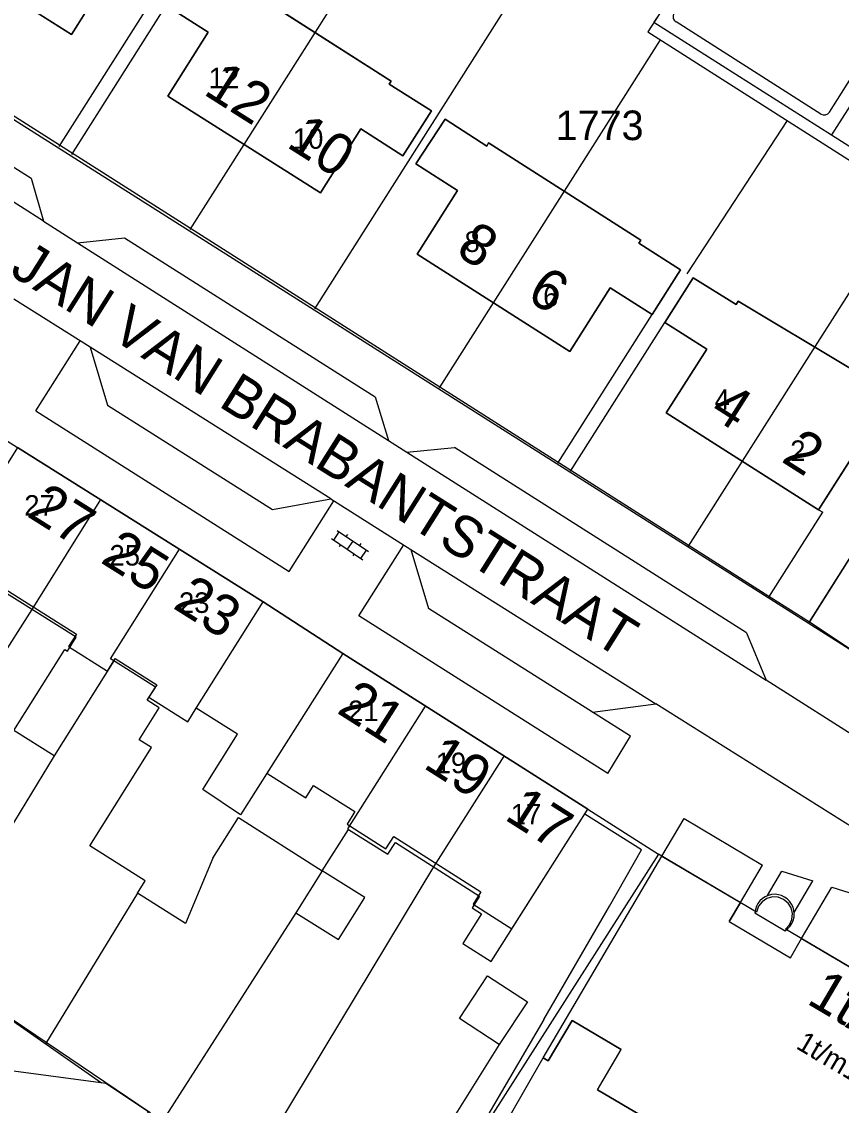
# Model space of a CAD drawing. Extents: x 148816 to 151297, y 399515 to 402500.
# Drawn here: x 149845.7 to 149895.6, y 400300.6 to 400366.5 of the extents above; entities that cross this region are included whole.
import ezdxf

# ---------------------------------------------------------------- set-up
doc = ezdxf.new("R2010")
doc.units = 0
for name, color, linetype in [('B01 Hoofdgebouw  [D] Norm', 7, 'Continuous'), ('B01 Hoofdgebouw  [T] Norm', 7, 'Continuous'), ('B01 hoofgebouw', 7, 'Continuous'), ('B02 Bijgebouw  [D] Norm', 7, 'Continuous'), ('B03 Overig opstal  [D] Norm', 7, 'Continuous'), ('B07 Tussenmuur  [D] Norm', 7, 'Continuous'), ('G01 perceelsgrens', 7, 'Continuous'), ('S02 Open verharding  Norm', 7, 'Continuous'), ('T04 Haag heg  [D] Gem', 7, 'Continuous'), ('V00 Kant verharding algemeen  [T] Norm', 7, 'Continuous'), ('V00 Kant verharding algemeen secundair  [T] Gem', 7, 'Continuous'), ('Z01 perceelnummer', 7, 'Continuous'), ('Z02 huisnummer', 7, 'Continuous'), ('Z02 Huisnummer  [Tekst] Norm', 7, 'Continuous'), ('Z06 straatnaam', 7, 'Continuous')]:
    doc.layers.add(name, color=color, linetype=linetype)

msp = doc.modelspace()

# ---------------------------------------------------------------- linework, layer by layer
at = {"layer": 'B01 Hoofdgebouw  [D] Norm'}
for p, q in [((149848.984, 400329.058), (149843.659, 400332.401)), ((149848.451, 400328.21), (149848.984, 400329.058)), ((149845.17, 400323.379), (149848.276, 400328.32)), ((149848.276, 400328.32), (149848.451, 400328.21)), ((149851.265, 400327.624), (149847.626, 400321.835)), ((149853.805, 400326.027), (149851.265, 400327.624)), ((149853.303, 400325.228), (149853.805, 400326.027)), ((149854.03, 400324.771), (149853.303, 400325.228)), ((149852.806, 400322.825), (149854.03, 400324.771)), ((149847.626, 400321.835), (149845.17, 400323.379)), ((149853.565, 400322.347), (149852.806, 400322.825)), ((149849.8, 400316.369), (149853.565, 400322.347)), ((149857.3, 400315.617), (149858.868, 400318.083)), ((149858.868, 400318.083), (149863.966, 400314.841)), ((149863.966, 400314.841), (149865.573, 400317.368)), ((149865.573, 400317.368), (149867.962, 400315.849)), ((149867.962, 400315.849), (149868.421, 400316.571)), ((149868.421, 400316.571), (149873.552, 400313.309)), ((149853.182, 400314.239), (149849.8, 400316.369)), ((149857.3, 400315.617), (149855.629, 400311.638)), ((149852.704, 400313.48), (149853.182, 400314.239)), ((149874.253, 400309.324), (149877.459, 400314.371)), ((149855.629, 400311.638), (149852.704, 400313.48)), ((149873.552, 400313.309), (149873.093, 400312.587)), ((149873.093, 400312.587), (149873.665, 400312.223)), ((149873.665, 400312.223), (149872.522, 400310.424)), ((149872.522, 400310.424), (149874.253, 400309.324))]:
    msp.add_line(p, q, dxfattribs=at)
at = {"layer": 'B01 Hoofdgebouw  [T] Norm'}
for p, q in [((149848.69, 400365.76), (149839.39, 400371.64)), ((149851.15, 400369.65), (149848.69, 400365.76)), ((149868.17, 400362.92), (149858.93, 400368.83)), ((149854.46, 400367.52), (149857.02, 400365.9)), ((149857.02, 400365.9), (149854.56, 400362.01)), ((149868.05, 400362.73), (149868.17, 400362.92)), ((149870.61, 400361.11), (149868.05, 400362.73)), ((149854.56, 400362.01), (149863.86, 400356.12)), ((149868.88, 400358.38), (149870.61, 400361.11)), ((149863.86, 400356.12), (149866.32, 400360.01)), ((149866.32, 400360.01), (149868.88, 400358.38)), ((149871.45, 400360.6), (149869.66, 400357.89)), ((149873.98, 400358.97), (149871.45, 400360.6)), ((149874.1, 400359.16), (149873.98, 400358.97)), ((149883.36, 400353.24), (149874.1, 400359.16)), ((149869.66, 400357.89), (149872.21, 400356.26)), ((149872.21, 400356.26), (149869.74, 400352.38)), ((149883.24, 400353.06), (149883.36, 400353.24)), ((149885.79, 400351.43), (149883.24, 400353.06)), ((149869.74, 400352.38), (149879.04, 400346.46)), ((149884.06, 400348.71), (149885.79, 400351.43)), ((149886.56, 400350.95), (149884.83, 400348.23)), ((149889.17, 400349.33), (149886.56, 400350.95)), ((149879.04, 400346.46), (149881.5, 400350.33)), ((149881.5, 400350.33), (149884.06, 400348.71)), ((149889.3, 400349.53), (149889.17, 400349.33)), ((149896.15, 400345.42), (149889.3, 400349.53)), ((149884.83, 400348.23), (149887.38, 400346.6)), ((149887.38, 400346.6), (149884.92, 400342.73)), ((149894.2, 400336.83), (149898.65, 400343.83)), ((149884.92, 400342.73), (149894.2, 400336.83)), ((149860.36, 400331.22), (149845.41, 400340.62)), ((149856.29, 400324.74), (149860.36, 400331.22)), ((149865.22, 400328.07), (149858.98, 400318.26)), ((149880.14, 400318.59), (149865.22, 400328.07)), ((149858.8, 400323.16), (149856.29, 400324.74)), ((149856.68, 400319.79), (149858.8, 400323.16)), ((149858.98, 400318.26), (149856.68, 400319.79)), ((149877.46, 400314.37), (149880.14, 400318.59))]:
    msp.add_line(p, q, dxfattribs=at)
msp.add_lwpolyline([(149887.45, 400297.544), (149880.725, 400301.507), (149882.178, 400303.971), (149879.188, 400305.734), (149877.735, 400303.27), (149877.418, 400303.458), (149884.655, 400315.734), (149889.444, 400312.91), (149888.759, 400311.747), (149892.479, 400309.553), (149893.165, 400310.717), (149902.365, 400305.293), (149901.679, 400304.13), (149905.4, 400301.936), (149906.085, 400303.099), (149914.976, 400297.862)], dxfattribs=at)
at = {"layer": 'B01 hoofgebouw'}
for points in [[(149848.69, 400365.76), (149851.15, 400369.65), (149853.71, 400368.03), (149855.45, 400370.73), (149852.9, 400372.36), (149853.01, 400372.54), (149843.72, 400378.48), (149843.59, 400378.27), (149841.02, 400379.89), (149839.29, 400377.15), (149841.85, 400375.53), (149839.39, 400371.64), (149848.69, 400365.76)], [(149858.93, 400368.83), (149868.17, 400362.92), (149868.05, 400362.73), (149870.61, 400361.11), (149868.88, 400358.38), (149866.32, 400360.01), (149863.86, 400356.12), (149854.56, 400362.01), (149857.02, 400365.9), (149854.46, 400367.52), (149856.19, 400370.25), (149858.81, 400368.62), (149858.93, 400368.83)], [(149869.66, 400357.89), (149871.45, 400360.6), (149873.98, 400358.97), (149874.1, 400359.16), (149883.36, 400353.24), (149883.24, 400353.06), (149885.79, 400351.43), (149884.06, 400348.71), (149881.5, 400350.33), (149879.04, 400346.46), (149869.74, 400352.38), (149872.21, 400356.26), (149869.66, 400357.89)], [(149894.2, 400336.83), (149884.92, 400342.73), (149887.38, 400346.6), (149884.83, 400348.23), (149886.56, 400350.95), (149889.17, 400349.33), (149889.3, 400349.53), (149896.15, 400345.42), (149898.65, 400343.83), (149894.2, 400336.83)], [(149877.46, 400314.37), (149880.14, 400318.59), (149865.22, 400328.07), (149858.98, 400318.26), (149856.68, 400319.79), (149858.8, 400323.16), (149856.29, 400324.74), (149860.36, 400331.22), (149845.41, 400340.62), (149839.23, 400330.78), (149837.06, 400332.15), (149834.4, 400327.91)], [(149840.836, 400333.337), (149843.202, 400331.844), (149843.683, 400332.604), (149848.99, 400329.254), (149848.51, 400328.494), (149850.877, 400327), (149851.357, 400327.761), (149853.884, 400326.166), (149853.404, 400325.406), (149855.77, 400323.912)], [(149855.77, 400323.912), (149856.29, 400324.74)], [(149860.588, 400320.788), (149862.954, 400319.284), (149863.438, 400320.045), (149865.956, 400318.445), (149865.473, 400317.684), (149867.839, 400316.181), (149868.323, 400316.941), (149873.63, 400313.569), (149873.147, 400312.809), (149875.513, 400311.305)], [(149877.418, 400303.458), (149884.655, 400315.734)], [(149884.655, 400315.734), (149889.444, 400312.91)], [(149875.513, 400311.305), (149877.46, 400314.37)], [(149888.759, 400311.747), (149889.444, 400312.91)], [(149888.759, 400311.747), (149892.479, 400309.553)], [(149892.479, 400309.553), (149893.165, 400310.717)], [(149893.165, 400310.717), (149902.365, 400305.293)], [(149877.735, 400303.27), (149879.188, 400305.734)], [(149879.188, 400305.734), (149882.178, 400303.971)], [(149880.725, 400301.507), (149882.178, 400303.971)], [(149877.418, 400303.458), (149877.735, 400303.27)], [(149880.725, 400301.507), (149887.45, 400297.544)]]:
    msp.add_lwpolyline(points, dxfattribs=at)
at = {"layer": 'B02 Bijgebouw  [D] Norm'}
for p, q in [((149859.21, 400359.065), (149863.544, 400365.908)), ((149874.39, 400349.42), (149878.719, 400356.22)), ((149889.56, 400339.78), (149894.011, 400346.78))]:
    msp.add_line(p, q, dxfattribs=at)
for points in [[(149863.966, 400314.841), (149862.36, 400312.283), (149864.946, 400310.659), (149866.552, 400313.217)], [(149876.46, 400306.873), (149874.748, 400304.259), (149872.328, 400305.844), (149874.04, 400308.458)]]:
    msp.add_lwpolyline(points, close=True, dxfattribs=at)
at = {"layer": 'B03 Overig opstal  [D] Norm'}
msp.add_line((149890.317, 400312.28), (149892.155, 400311.197), dxfattribs=at)
msp.add_arc((149891.515, 400312.212), 1.2, 302.21096, 176.77184, dxfattribs=at)
at = {"layer": 'B07 Tussenmuur  [D] Norm'}
for p, q in [((149850.465, 400337.444), (149846.268, 400330.762)), ((149850.465, 400337.444), (149846.268, 400330.762)), ((149870.759, 400315.083), (149875.044, 400321.827)), ((149870.759, 400315.083), (149875.044, 400321.827))]:
    msp.add_line(p, q, dxfattribs=at)
for points in [[(149851.265, 400327.624), (149851.069, 400327.746), (149855.266, 400334.428)], [(149851.265, 400327.624), (149851.069, 400327.746), (149855.266, 400334.428)], [(149865.573, 400317.368), (149865.516, 400317.404), (149870.258, 400324.868)], [(149865.573, 400317.368), (149865.516, 400317.404), (149870.258, 400324.868)]]:
    msp.add_lwpolyline(points, dxfattribs=at)
at = {"layer": 'G01 perceelsgrens'}
for points in [[(149884.51, 400367.023), (149883.805, 400365.913)], [(149883.805, 400365.913), (149904.374, 400352.835)], [(149840.789, 400363.581), (149890.949, 400331.716)], [(149834.363, 400347.633), (149839.34, 400344.48), (149845.41, 400340.62), (149860.36, 400331.22), (149865.22, 400328.07), (149880.14, 400318.59), (149884.445, 400315.855)], [(149893.653, 400329.997), (149900.118, 400340.229), (149902.805, 400344.404)], [(149890.949, 400331.716), (149893.653, 400329.997)], [(149893.653, 400329.997), (149896.309, 400328.234)], [(149825.415, 400300.146), (149825.586, 400301.131), (149828.356, 400317.096), (149853.483, 400300.138), (149854.231, 400298.37)], [(149884.445, 400315.855), (149871.351, 400295.348)], [(149890.422, 400312.334), (149884.445, 400315.855)], [(149892.188, 400311.293), (149892.431, 400311.559), (149892.573, 400311.882), (149892.606, 400312.235), (149892.524, 400312.581), (149892.341, 400312.878), (149892.067, 400313.106), (149891.737, 400313.235), (149891.381, 400313.251), (149891.041, 400313.154), (149890.753, 400312.959), (149890.541, 400312.683)], [(149890.541, 400312.683), (149890.422, 400312.334)], [(149903.342, 400304.716), (149892.188, 400311.293)]]:
    msp.add_lwpolyline(points, dxfattribs=at)
at = {"layer": 'S02 Open verharding  Norm'}
for p, q in [((149864.536, 400335.065), (149866.443, 400333.779)), ((149864.66, 400334.981), (149864.996, 400335.479)), ((149864.871, 400335.563), (149866.778, 400334.277)), ((149865.494, 400335.324), (149865.41, 400335.199)), ((149865.075, 400334.702), (149864.991, 400334.577)), ((149865.825, 400334.92), (149865.489, 400334.422)), ((149866.323, 400334.765), (149866.239, 400334.64)), ((149866.318, 400333.863), (149866.654, 400334.361)), ((149865.904, 400334.143), (149865.82, 400334.018))]:
    msp.add_line(p, q, dxfattribs=at)
at = {"layer": 'T04 Haag heg  [D] Gem'}
for p, q in [((149863.544, 400365.908), (149870.025, 400376.115)), ((149863.508, 400349.06), (149877.671, 400371.368)), ((149878.719, 400356.22), (149884.566, 400365.429)), ((149892.285, 400360.521), (149886.177, 400351.193)), ((149855.917, 400353.879), (149859.21, 400359.065)), ((149894.011, 400346.78), (149899.73, 400355.788)), ((149871.1, 400344.239), (149874.39, 400349.42)), ((149886.274, 400334.604), (149889.56, 400339.78)), ((149893.62, 400329.944), (149896.89, 400335.12)), ((149846.268, 400330.762), (149835.655, 400314.035)), ((149847.626, 400321.835), (149839.973, 400309.278)), ((149852.704, 400313.48), (149847.105, 400304.304)), ((149862.36, 400312.283), (149854.115, 400299.414))]:
    msp.add_line(p, q, dxfattribs=at)
for points in [[(149850.524, 400301.919), (149836.857, 400311.452), (149826.971, 400315.425), (149831.002, 400323.201), (149843.277, 400341.976)], [(149866.276, 400291.846), (149858.413, 400294.609), (149870.759, 400315.083)], [(149874.748, 400304.259), (149866.926, 400291.768)]]:
    msp.add_lwpolyline(points, dxfattribs=at)
at = {"layer": 'V00 Kant verharding algemeen  [T] Norm'}
for p, q in [((149799.713, 400389.358), (149913.68, 400317.203)), ((149821.654, 400372.606), (149846.228, 400357.003)), ((149847.941, 400358.944), (149853.71, 400368.03)), ((149848.706, 400358.458), (149854.46, 400367.52)), ((149846.228, 400357.003), (149846.99, 400354.388)), ((149846.99, 400354.388), (149849.063, 400353.072)), ((149849.063, 400353.072), (149851.928, 400353.384)), ((149851.928, 400353.384), (149867.185, 400343.696)), ((149849.826, 400346.722), (149845.176, 400349.65)), ((149878.313, 400339.659), (149884.06, 400348.71)), ((149879.079, 400339.173), (149884.83, 400348.23)), ((149846.524, 400342.845), (149849.224, 400347.101)), ((149849.826, 400346.722), (149850.876, 400343.2)), ((149867.185, 400343.696), (149868.004, 400341.045)), ((149846.524, 400342.845), (149861.939, 400333.072)), ((149850.876, 400343.2), (149860.942, 400336.831)), ((149868.004, 400341.045), (149869.113, 400340.341)), ((149869.113, 400340.341), (149872.024, 400340.624)), ((149889.813, 400329.329), (149872.024, 400340.624)), ((149860.942, 400336.831), (149864.491, 400337.485)), ((149861.939, 400333.072), (149864.667, 400337.374)), ((149864.491, 400337.485), (149869.367, 400334.414)), ((149891.169, 400331.496), (149894.453, 400336.669)), ((149894.2, 400336.83), (149894.453, 400336.669)), ((149866.199, 400330.371), (149868.934, 400334.687)), ((149869.367, 400334.413), (149870.441, 400330.821)), ((149865.22, 400328.07), (149860.36, 400331.22)), ((149881.36, 400320.76), (149866.199, 400330.371)), ((149882.74, 400323.04), (149870.441, 400330.821)), ((149889.813, 400329.329), (149890.999, 400326.445)), ((149898.14, 400321.91), (149890.999, 400326.445)), ((149880.435, 400324.498), (149884.29, 400325.015)), ((149899.62, 400315.36), (149884.29, 400325.015)), ((149881.36, 400320.76), (149882.74, 400323.04)), ((149889.444, 400312.91), (149890.789, 400315.191)), ((149891.088, 400313.333), (149891.964, 400314.819)), ((149892.711, 400312.31), (149893.84, 400314.226)), ((149893.165, 400310.717), (149895.014, 400313.855)), ((149877.454, 400305.795), (149881.465, 400312.682))]:
    msp.add_line(p, q, dxfattribs=at)
for points in [[(149884.51, 400367.023), (149884.17, 400366.511), (149894.985, 400359.648)], [(149894.342, 400360.914), (149885.514, 400366.523)], [(149894.86, 400361.038), (149896.677, 400363.892)], [(149897.391, 400363.425), (149894.975, 400359.651), (149907.507, 400351.709), (149908.564, 400353.496), (149909.089, 400353.659), (149925.54, 400348.921), (149929.726, 400345.127), (149929.347, 400343.684), (149927.069, 400346.271), (149911.693, 400352.341), (149911.699, 400352.341)], [(149881.465, 400312.682), (149883.416, 400316.11), (149879.956, 400318.3)], [(149884.655, 400315.734), (149886.006, 400318.021), (149890.789, 400315.191)], [(149891.964, 400314.819), (149893.84, 400314.226)], [(149895.014, 400313.855), (149905.464, 400310.55)], [(149855.196, 400291.768), (149853.333, 400300.181), (149850.786, 400301.884), (149825.66, 400305.246), (149821.242, 400272.229), (149844.178, 400269.335), (149853.581, 400236.253)], [(149877.454, 400305.795), (149869.096, 400291.507)], [(149870.331, 400291.09), (149877.418, 400303.458)]]:
    msp.add_lwpolyline(points, dxfattribs=at)
for centre, radius, start, end in [((149885.718, 400366.85), 0.386, 147.76752, 238.01751), ((149894.518, 400361.283), 0.421, 243.35732, 324.35946)]:
    msp.add_arc(centre, radius, start, end, dxfattribs=at)
at = {"layer": 'V00 Kant verharding algemeen secundair  [T] Gem'}
for p, q in [((149846.99, 400354.388), (149818.816, 400372.278)), ((149849.063, 400353.072), (149868.004, 400341.045)), ((149864.49, 400337.485), (149849.826, 400346.721)), ((149869.113, 400340.341), (149891, 400326.443)), ((149869.367, 400334.413), (149884.29, 400325.015))]:
    msp.add_line(p, q, dxfattribs=at)

# ---------------------------------------------------------------- texts
at = {"layer": 'Z01 perceelnummer'}
msp.add_text('1773', height=1.8, dxfattribs=at).set_placement((149878.179, 400359.33))
at = {"layer": 'Z02 huisnummer'}
for s, rotation, p in [('12', 327.66062, (149856.654, 400362.163)), ('10', 327.66062, (149861.714, 400358.958)), ('8', 327.5332, (149872.017, 400352.411)), ('6', 327.5332, (149876.322, 400349.671)), ('4', 327.5332, (149887.475, 400342.586)), ('2', 327.5332, (149891.857, 400339.799)), ('27', 327.8671, (149845.897, 400336.473)), ('25', 327.8671, (149850.384, 400333.653)), ('23', 327.8671, (149854.794, 400330.879)), ('21', 327.58155, (149864.778, 400324.499)), ('19', 327.58155, (149870.043, 400321.154)), ('17', 327.58155, (149874.986, 400318.014)), ('1t/m15', 329.4589, (149893.397, 400306.807))]:
    msp.add_text(s, height=2.5, rotation=rotation, dxfattribs=at).set_placement(p)
at = {"layer": 'Z02 Huisnummer  [Tekst] Norm'}
for s, p in [('12', (149857.048, 400362.485)), ('10', (149862.173, 400358.801)), ('8', (149872.63, 400352.521)), ('6', (149877.419, 400349.208)), ('4', (149887.863, 400342.914)), ('2', (149892.47, 400339.796)), ('27', (149845.815, 400336.465)), ('25', (149851.005, 400333.428)), ('23', (149855.235, 400330.545)), ('21', (149865.54, 400323.96)), ('19', (149870.871, 400320.787)), ('17', (149875.445, 400317.665))]:
    msp.add_text(s, height=1.25, dxfattribs=at).set_placement(p)
msp.add_text('1t/m15', height=1.25, rotation=329.4589, dxfattribs=at).set_placement((149892.76, 400304.064))
at = {"layer": 'Z06 straatnaam'}
msp.add_text('JAN VAN BRABANTSTRAAT', height=2.5, rotation=327.7881, dxfattribs=at).set_placement((149844.843, 400351.191))

doc.saveas('drawing.dxf')
